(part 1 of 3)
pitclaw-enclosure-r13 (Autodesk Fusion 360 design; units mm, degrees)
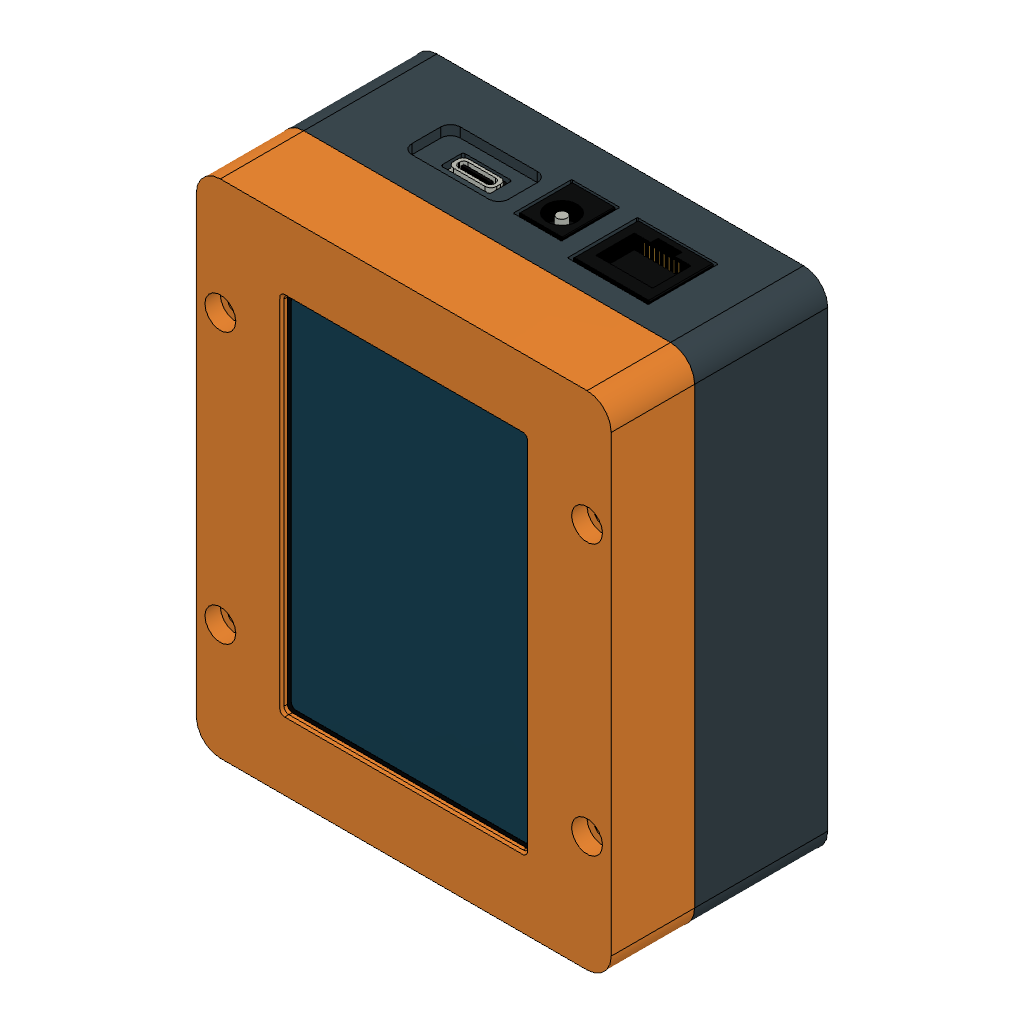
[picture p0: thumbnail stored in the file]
description: Part Number
part number: D_DO-41_SOD81_P10.16mm_Horizontal
part number: R_Axial_DIN0207_L6.3mm_D2.5mm_P7.62mm_Horizontal
part number: PinHeader_1x02_P2.54mm_Vertical
part number: TO-92_Inline_Wide
part number: JST_XH_B2B-XH-A_1x02_P2.50mm_Vertical
part number: JST_XH_B8B-XH-A_1x08_P2.50mm_Vertical
part number: pitclaw-carrier_pad
part number: pitclaw-carrier_silkscreen
part number: pitclaw-carrier_soldermask
parameter "floor_t" = 2.5 comment "PitClaw r8 nominal assembly datum; recheck fit after editing"
parameter "carrier_standoff" = 5 comment "PitClaw r8 nominal assembly datum; recheck fit after editing"
parameter "seam_z" = 27.6 comment "PitClaw r8 nominal assembly datum; recheck fit after editing"
parameter "case_h" = 44.9 comment "PitClaw r8 nominal assembly datum; recheck fit after editing"
parameter "retainer_t" = 2.5 comment "PitClaw r8 nominal assembly datum; recheck fit after editing"
parameter "retainer_top" = 32.6 comment "PitClaw r8 nominal assembly datum; recheck fit after editing"
parameter "retainer_bottom" = 30.1 (= "retainer_top - retainer_t") comment "PitClaw r8 nominal assembly datum; recheck fit after editing"
parameter "insert_pilot" = 4.2 comment "PitClaw r8 nominal assembly datum; recheck fit after editing"
parameter "insert_depth" = 5 comment "PitClaw r8 nominal assembly datum; recheck fit after editing"
parameter "lip_h" = 2 comment "PitClaw r8 nominal assembly datum; recheck fit after editing"
sketch "Outer shell profile" plane through (0, 0, 0) normal (0, 0, 1) x axis (1, 0, 0)
  line L1 (38, -52) -> (-38, -52)
  line L2 (43, 47) -> (43, -47)
  line L3 (-38, 52) -> (38, 52)
  line L4 (-43, -47) -> (-43, 47)
  arc A1 centre (38, -47) radius 5 clockwise from (43, -47) to (38, -52)
  arc A2 centre (38, 47) radius 5 clockwise from (38, 52) to (43, 47)
  arc A3 centre (-38, 47) radius 5 clockwise from (-43, 47) to (-38, 52)
  arc A4 centre (-38, -47) radius 5 clockwise from (-38, -52) to (-43, -47)
extrude "Extrude1" new body sketch "Outer shell profile" along normal blind 27.6 (= "seam_z") bodies "01 Bottom shell"
sketch "Open cavity profile" plane through (0, 0, 0) normal (0, 0, 1) x axis (1, 0, 0)
  line L1 (38, -49.5) -> (-38, -49.5)
  line L2 (40.5, 47) -> (40.5, -47)
  line L3 (-38, 49.5) -> (38, 49.5)
  line L4 (-40.5, -47) -> (-40.5, 47)
  arc A1 centre (38, -47) radius 2.5 clockwise from (40.5, -47) to (38, -49.5)
  arc A2 centre (38, 47) radius 2.5 clockwise from (38, 49.5) to (40.5, 47)
  arc A3 centre (-38, 47) radius 2.5 clockwise from (-40.5, 47) to (-38, 49.5)
  arc A4 centre (-38, -47) radius 2.5 clockwise from (-38, -49.5) to (-40.5, -47)
extrude "Extrude2" cut sketch "Open cavity profile" blind 27.6 (= "seam_z") from offset 2.5 (= "floor_t")
sketch "Four carrier insert bosses profile" plane through (0, 0, 0) normal (0, 0, 1) x axis (1, 0, 0)
  circle C1 centre (-25.5, -37) radius 4.5
  circle C2 centre (-25.5, 21) radius 4.5
  circle C3 centre (25.5, -37) radius 4.5
  circle C4 centre (25.5, 21) radius 4.5
extrude "Extrude3" add sketch "Four carrier insert bosses profile" blind 5 (= "carrier_standoff") from offset 2.5 (= "floor_t")
sketch "Four case closure columns profile" plane through (0, 0, 0) normal (0, 0, 1) x axis (1, 0, 0)
  circle C1 centre (-38, -28) radius 4.5
  circle C2 centre (-38, 28) radius 4.5
  circle C3 centre (38, -28) radius 4.5
  circle C4 centre (38, 28) radius 4.5
extrude "Extrude4" add sketch "Four case closure columns profile" blind 25.1 (= "seam_z - floor_t") from offset 2.5 (= "floor_t")
sketch "USB recess internal backing profile" plane through (0, 0, 0) normal (0, 1, 0) x axis (1, 0, 0)
  line L1 (22.5, -10.7) -> (6.5, -10.7)
  line L2 (24.5, -18.7) -> (24.5, -12.7)
  line L3 (6.5, -20.7) -> (22.5, -20.7)
  line L4 (4.5, -12.7) -> (4.5, -18.7)
  arc A1 centre (22.5, -12.7) radius 2 clockwise from (22.5, -10.7) to (24.5, -12.7)
  arc A2 centre (22.5, -18.7) radius 2 clockwise from (24.5, -18.7) to (22.5, -20.7)
  arc A3 centre (6.5, -18.7) radius 2 clockwise from (6.5, -20.7) to (4.5, -18.7)
  arc A4 centre (6.5, -12.7) radius 2 clockwise from (4.5, -12.7) to (6.5, -10.7)
extrude "Extrude5" add sketch "USB recess internal backing profile" blind 1.02 from offset 48.5
sketch "Carrier insert pilots profile" plane through (0, 0, 0) normal (0, 0, 1) x axis (1, 0, 0)
  circle C1 centre (-25.5, -37) radius 2.1
  circle C2 centre (-25.5, 21) radius 2.1
  circle C3 centre (25.5, -37) radius 2.1
  circle C4 centre (25.5, 21) radius 2.1
  dimension "d127" diameter C1 = 4.2 (= "insert_pilot")
  dimension "d128" diameter C2 = 4.2 (= "insert_pilot")
  dimension "d129" diameter C3 = 4.2 (= "insert_pilot")
  dimension "d130" diameter C4 = 4.2 (= "insert_pilot")
extrude "Extrude6" cut sketch "Carrier insert pilots profile" blind 5.02 from offset 2.5 (= "floor_t")
sketch "Closure insert pilots profile" plane through (0, 0, 0) normal (0, 0, 1) x axis (1, 0, 0)
  circle C1 centre (-38, -28) radius 2.1
  circle C2 centre (-38, 28) radius 2.1
  circle C3 centre (38, -28) radius 2.1
  circle C4 centre (38, 28) radius 2.1
  dimension "d131" diameter C1 = 4.2 (= "insert_pilot")
  dimension "d132" diameter C2 = 4.2 (= "insert_pilot")
  dimension "d133" diameter C3 = 4.2 (= "insert_pilot")
  dimension "d134" diameter C4 = 4.2 (= "insert_pilot")
extrude "Extrude7" cut sketch "Closure insert pilots profile" blind 5.02 from offset 22.6 (= "seam_z - insert_depth")
sketch "Three probe access holes profile" plane through (0, 0, 0) normal (0, 1, 0) x axis (1, 0, 0)
  circle C1 centre (-17, -11.65) radius 5.25
  circle C2 centre (0, -11.65) radius 5.25
  circle C3 centre (17, -11.65) radius 5.25
extrude "Extrude8" cut sketch "Three probe access holes profile" blind 10 from offset -57
sketch "RJ45 fitted opening profile" plane through (0, 0, 0) normal (0, 1, 0) x axis (1, 0, 0)
  line L1 (-12.325, -8.6) -> (-28.675, -8.6)
  line L2 (-12.125, -22.91) -> (-12.125, -8.8)
  line L3 (-28.675, -23.11) -> (-12.325, -23.11)
  line L4 (-28.875, -8.8) -> (-28.875, -22.91)
  arc A1 centre (-12.325, -8.8) radius 0.2 clockwise from (-12.325, -8.6) to (-12.125, -8.8)
  arc A2 centre (-12.325, -22.91) radius 0.2 clockwise from (-12.125, -22.91) to (-12.325, -23.11)
  arc A3 centre (-28.675, -22.91) radius 0.2 clockwise from (-28.675, -23.11) to (-28.875, -22.91)
  arc A4 centre (-28.675, -8.8) radius 0.2 clockwise from (-28.875, -8.8) to (-28.675, -8.6)
extrude "Extrude9" cut sketch "RJ45 fitted opening profile" blind 10 from offset 47
sketch "Barrel fitted opening profile" plane through (0, 0, 0) normal (0, 1, 0) x axis (1, 0, 0)
  line L1 (1.3, -8.6) -> (-8.3, -8.6)
  line L2 (1.5, -20.5) -> (1.5, -8.8)
  line L3 (-8.3, -20.7) -> (1.3, -20.7)
  line L4 (-8.5, -8.8) -> (-8.5, -20.5)
  arc A1 centre (1.3, -8.8) radius 0.2 clockwise from (1.3, -8.6) to (1.5, -8.8)
  arc A2 centre (1.3, -20.5) radius 0.2 clockwise from (1.5, -20.5) to (1.3, -20.7)
  arc A3 centre (-8.3, -20.5) radius 0.2 clockwise from (-8.3, -20.7) to (-8.5, -20.5)
  arc A4 centre (-8.3, -8.8) radius 0.2 clockwise from (-8.5, -8.8) to (-8.3, -8.6)
extrude "Extrude10" cut sketch "Barrel fitted opening profile" blind 10 from offset 47
sketch "USB fitted shell aperture profile" plane through (0, 0, 0) normal (0, 1, 0) x axis (1, 0, 0)
  line L1 (19.17, -13) -> (9.83, -13)
  line L2 (19.57, -17.3) -> (19.57, -13.4)
  line L3 (9.83, -17.7) -> (19.17, -17.7)
  line L4 (9.43, -13.4) -> (9.43, -17.3)
  arc A1 centre (19.17, -13.4) radius 0.4 clockwise from (19.17, -13) to (19.57, -13.4)
  arc A2 centre (19.17, -17.3) radius 0.4 clockwise from (19.57, -17.3) to (19.17, -17.7)
  arc A3 centre (9.83, -17.3) radius 0.4 clockwise from (9.83, -17.7) to (9.43, -17.3)
  arc A4 centre (9.83, -13.4) radius 0.4 clockwise from (9.43, -13.4) to (9.83, -13)
extrude "Extrude11" cut sketch "USB fitted shell aperture profile" blind 10 from offset 47
sketch "USB shallow external recess profile" plane through (0, 0, 0) normal (0, 1, 0) x axis (1, 0, 0)
  line L1 (22.5, -10.7) -> (6.5, -10.7)
  line L2 (24.5, -18.7) -> (24.5, -12.7)
  line L3 (6.5, -20.7) -> (22.5, -20.7)
  line L4 (4.5, -12.7) -> (4.5, -18.7)
  arc A1 centre (22.5, -12.7) radius 2 clockwise from (22.5, -10.7) to (24.5, -12.7)
  arc A2 centre (22.5, -18.7) radius 2 clockwise from (24.5, -18.7) to (22.5, -20.7)
  arc A3 centre (6.5, -18.7) radius 2 clockwise from (6.5, -20.7) to (4.5, -18.7)
  arc A4 centre (6.5, -12.7) radius 2 clockwise from (4.5, -12.7) to (6.5, -10.7)
extrude "Extrude12" cut sketch "USB shallow external recess profile" blind 2.02 from offset 50
sketch "Hidden carrier edge channel profile" plane through (0, 0, 0) normal (0, 0, 1) x axis (1, 0, 0)
  line L1 (30.5, 49.48) -> (-30.5, 49.48)
  line L2 (30.5, 51) -> (30.5, 49.48)
  line L3 (-30.5, 51) -> (30.5, 51)
  line L4 (-30.5, 49.48) -> (-30.5, 51)
extrude "Extrude13" cut sketch "Hidden carrier edge channel profile" blind 2.9 from offset 7
sketch "Hidden USB PCB edge clearance profile" plane through (0, 0, 0) normal (0, 0, 1) x axis (1, 0, 0)
  line L1 (24.86, 48.48) -> (4.14, 48.48)
  line L2 (24.86, 49.057) -> (24.86, 48.48)
  line L3 (4.14, 49.057) -> (24.86, 49.057)
  line L4 (4.14, 48.48) -> (4.14, 49.057)
extrude "Extrude14" cut sketch "Hidden USB PCB edge clearance profile" blind 3.5 from offset 11.3
sketch "Hidden USB spacer and head clearances profile" plane through (0, 0, 0) normal (0, 0, 1) x axis (1, 0, 0)
  circle C1 centre (6.753, 46.317) radius 2.7
  circle C2 centre (21.993, 46.317) radius 2.7
extrude "Extrude15" cut sketch "Hidden USB spacer and head clearances profile" blind 8.5 from offset 8.3
sketch "Power edge support -28 profile" plane through (0, 0, 0) normal (0, 0, 1) x axis (1, 0, 0)
  line L1 (-25, 49.2) -> (-28, 49.2)
  line L2 (-25, 50.5) -> (-25, 49.2)
  line L3 (-28, 50.5) -> (-25, 50.5)
  line L4 (-28, 49.2) -> (-28, 50.5)
extrude "Extrude16" add sketch "Power edge support -28 profile" blind 5 (= "carrier_standoff") from offset 2.5 (= "floor_t")
sketch "Power edge support 26 profile" plane through (0, 0, 0) normal (0, 0, 1) x axis (1, 0, 0)
  line L1 (29, 49.2) -> (26, 49.2)
  line L2 (29, 50.5) -> (29, 49.2)
  line L3 (26, 50.5) -> (29, 50.5)
  line L4 (26, 49.2) -> (26, 50.5)
extrude "Extrude17" add sketch "Power edge support 26 profile" blind 5 (= "carrier_standoff") from offset 2.5 (= "floor_t")
sketch "Top outer cup profile" plane through (0, 0, 0) normal (0, 0, 1) x axis (1, 0, 0)
  line L1 (38, -52) -> (-38, -52)
  line L2 (43, 47) -> (43, -47)
  line L3 (-38, 52) -> (38, 52)
  line L4 (-43, -47) -> (-43, 47)
  arc A1 centre (38, -47) radius 5 clockwise from (43, -47) to (38, -52)
  arc A2 centre (38, 47) radius 5 clockwise from (38, 52) to (43, 47)
  arc A3 centre (-38, 47) radius 5 clockwise from (-43, 47) to (-38, 52)
  arc A4 centre (-38, -47) radius 5 clockwise from (-38, -52) to (-43, -47)
extrude "Extrude1" new body sketch "Top outer cup profile" blind 17.3 (= "case_h - seam_z") from offset 27.6 (= "seam_z") bodies "02 Top bezel - fitted lip and 4.2mm pilots"
sketch "Top inner cavity profile" plane through (0, 0, 0) normal (0, 0, 1) x axis (1, 0, 0)
  line L1 (38, -49.5) -> (-38, -49.5)
  line L2 (40.5, 47) -> (40.5, -47)
  line L3 (-38, 49.5) -> (38, 49.5)
  line L4 (-40.5, -47) -> (-40.5, 47)
  arc A1 centre (38, -47) radius 2.5 clockwise from (40.5, -47) to (38, -49.5)
  arc A2 centre (38, 47) radius 2.5 clockwise from (38, 49.5) to (40.5, 47)
  arc A3 centre (-38, 47) radius 2.5 clockwise from (-40.5, 47) to (-38, 49.5)
  arc A4 centre (-38, -47) radius 2.5 clockwise from (-38, -49.5) to (-40.5, -47)
extrude "Extrude2" cut sketch "Top inner cavity profile" blind 14.32 (= "case_h - 3 mm - seam_z + 0.02 mm") from offset 27.58 (= "seam_z - 0.02 mm")
sketch "Locating lip connecting shoulder profile" plane through (0, 0, 0) normal (0, 0, 1) x axis (1, 0, 0)
  line L1 (38, -52) -> (-38, -52)
  line L2 (43, 47) -> (43, -47)
  line L3 (-38, 52) -> (38, 52)
  line L4 (-43, -47) -> (-43, 47)
  line L5 (35, -48) -> (-35, -48)
  line L6 (39, 44) -> (39, -44)
  line L7 (-35, 48) -> (35, 48)
  line L8 (-39, -44) -> (-39, 44)
  arc A1 centre (38, -47) radius 5 clockwise from (43, -47) to (38, -52)
  arc A2 centre (38, 47) radius 5 clockwise from (38, 52) to (43, 47)
  arc A3 centre (-38, 47) radius 5 clockwise from (-43, 47) to (-38, 52)
  arc A4 centre (-38, -47) radius 5 clockwise from (-38, -52) to (-43, -47)
  arc A5 centre (35, -44) radius 4 clockwise from (39, -44) to (35, -48)
  arc A6 centre (35, 44) radius 4 clockwise from (35, 48) to (39, 44)
  arc A7 centre (-35, 44) radius 4 clockwise from (-39, 44) to (-35, 48)
  arc A8 centre (-35, -44) radius 4 clockwise from (-35, -48) to (-39, -44)
extrude "Extrude3" add sketch "Locating lip connecting shoulder profile" blind 1 from offset 27.6 (= "seam_z")
sketch "Locating lip profile" plane through (0, 0, 0) normal (0, 0, 1) x axis (1, 0, 0)
  line L1 (38.2, -49.2) -> (-38.2, -49.2)
  line L2 (40.2, 47.2) -> (40.2, -47.2)
  line L3 (-38.2, 49.2) -> (38.2, 49.2)
  line L4 (-40.2, -47.2) -> (-40.2, 47.2)
  line L5 (38, -48) -> (-38, -48)
  line L6 (39, 47) -> (39, -47)
  line L7 (-38, 48) -> (38, 48)
  line L8 (-39, -47) -> (-39, 47)
  arc A1 centre (38.2, -47.2) radius 2 clockwise from (40.2, -47.2) to (38.2, -49.2)
  arc A2 centre (38.2, 47.2) radius 2 clockwise from (38.2, 49.2) to (40.2, 47.2)
  arc A3 centre (-38.2, 47.2) radius 2 clockwise from (-40.2, 47.2) to (-38.2, 49.2)
  arc A4 centre (-38.2, -47.2) radius 2 clockwise from (-38.2, -49.2) to (-40.2, -47.2)
  arc A5 centre (38, -47) radius 1 clockwise from (39, -47) to (38, -48)
  arc A6 centre (38, 47) radius 1 clockwise from (38, 48) to (39, 47)
  arc A7 centre (-38, 47) radius 1 clockwise from (-39, 47) to (-38, 48)
  arc A8 centre (-38, -47) radius 1 clockwise from (-38, -48) to (-39, -47)
extrude "Extrude4" add sketch "Locating lip profile" blind 2.02 (= "lip_h + 0.02 mm") from offset 25.6 (= "seam_z - lip_h")
sketch "Lip relief around closure columns profile" plane through (0, 0, 0) normal (0, 0, 1) x axis (1, 0, 0)
  circle C1 centre (-38, -28) radius 5
  circle C2 centre (-38, 28) radius 5
  circle C3 centre (38, -28) radius 5
  circle C4 centre (38, 28) radius 5
extrude "Extrude5" cut sketch "Lip relief around closure columns profile" blind 2.02 (= "lip_h + 0.02 mm") from offset 25.58 (= "seam_z - lip_h - 0.02 mm")
sketch "Four independent closure columns profile" plane through (0, 0, 0) normal (0, 0, 1) x axis (1, 0, 0)
  circle C1 centre (-38, -28) radius 4.5
  circle C2 centre (-38, 28) radius 4.5
  circle C3 centre (38, -28) radius 4.5
  circle C4 centre (38, 28) radius 4.5
extrude "Extrude6" add sketch "Four independent closure columns profile" blind 17.3 (= "case_h - seam_z") from offset 27.6 (= "seam_z")
sketch "Four display retainer hard stops profile" plane through (0, 0, 0) normal (0, 0, 1) x axis (1, 0, 0)
  circle C1 centre (-35.5, -40) radius 4.5
  circle C2 centre (-35.5, 40) radius 4.5
  circle C3 centre (35.5, -40) radius 4.5
  circle C4 centre (35.5, 40) radius 4.5
extrude "Extrude7" add sketch "Four display retainer hard stops profile" blind 12.3 (= "case_h - retainer_top") from offset 32.6 (= "retainer_top")
sketch "Display body and glass pocket profile" plane through (0, 0, 0) normal (0, 0, 1) x axis (1, 0, 0)
  line L1 (29.1, -46.6) -> (-29.1, -46.6)
  line L2 (30.6, 45.1) -> (30.6, -45.1)
  line L3 (-29.1, 46.6) -> (29.1, 46.6)
  line L4 (-30.6, -45.1) -> (-30.6, 45.1)
  arc A1 centre (29.1, -45.1) radius 1.5 clockwise from (30.6, -45.1) to (29.1, -46.6)
  arc A2 centre (29.1, 45.1) radius 1.5 clockwise from (29.1, 46.6) to (30.6, 45.1)
  arc A3 centre (-29.1, 45.1) radius 1.5 clockwise from (-30.6, 45.1) to (-29.1, 46.6)
  arc A4 centre (-29.1, -45.1) radius 1.5 clockwise from (-29.1, -46.6) to (-30.6, -45.1)
extrude "Extrude8" cut sketch "Display body and glass pocket profile" blind 16.12 from offset 27.58 (= "seam_z - 0.02 mm")
sketch "Active display window profile" plane through (0, 0, 0) normal (0, 0, 1) x axis (1, 0, 0)
  line L1 (24.3, -37.55) -> (-24.3, -37.55)
  line L2 (25.3, 36.55) -> (25.3, -36.55)
  line L3 (-24.3, 37.55) -> (24.3, 37.55)
  line L4 (-25.3, -36.55) -> (-25.3, 36.55)
  arc A1 centre (24.3, -36.55) radius 1 clockwise from (25.3, -36.55) to (24.3, -37.55)
  arc A2 centre (24.3, 36.55) radius 1 clockwise from (24.3, 37.55) to (25.3, 36.55)
  arc A3 centre (-24.3, 36.55) radius 1 clockwise from (-25.3, 36.55) to (-24.3, 37.55)
  arc A4 centre (-24.3, -36.55) radius 1 clockwise from (-24.3, -37.55) to (-25.3, -36.55)
extrude "Extrude9" cut sketch "Active display window profile" blind 1.24 from offset 43.68
work_plane "WorkPlane1" AlongDistance 44.4 ExtraOffset 0
sketch "Front window bevel start profile" plane through (0, 0, 44.4) normal (0, 0, 1) x axis (1, 0, 0)
  line L1 (24.3, -37.55) -> (-24.3, -37.55)
  line L2 (25.3, 36.55) -> (25.3, -36.55)
  line L3 (-24.3, 37.55) -> (24.3, 37.55)
  line L4 (-25.3, -36.55) -> (-25.3, 36.55)
  arc A1 centre (24.3, -36.55) radius 1 clockwise from (25.3, -36.55) to (24.3, -37.55)
  arc A2 centre (24.3, 36.55) radius 1 clockwise from (24.3, 37.55) to (25.3, 36.55)
  arc A3 centre (-24.3, 36.55) radius 1 clockwise from (-25.3, 36.55) to (-24.3, 37.55)
  arc A4 centre (-24.3, -36.55) radius 1 clockwise from (-24.3, -37.55) to (-25.3, -36.55)
work_plane "WorkPlane2" AlongDistance 44.92 ExtraOffset 0
sketch "Front window bevel end profile" plane through (0, 0, 44.92) normal (0, 0, 1) x axis (1, 0, 0)
  line L1 (24.6695, -37.9255) -> (-24.6695, -37.9255)
  line L2 (25.6795, 36.9155) -> (25.6795, -36.9155)
  line L3 (-24.6695, 37.9255) -> (24.6695, 37.9255)
  line L4 (-25.6795, -36.9155) -> (-25.6795, 36.9155)
  arc A1 centre (24.6695, -36.9155) radius 1.01 clockwise from (25.6795, -36.9155) to (24.6695, -37.9255)
  arc A2 centre (24.6695, 36.9155) radius 1.01 clockwise from (24.6695, 37.9255) to (25.6795, 36.9155)
  arc A3 centre (-24.6695, 36.9155) radius 1.01 clockwise from (-25.6795, 36.9155) to (-24.6695, 37.9255)
  arc A4 centre (-24.6695, -36.9155) radius 1.01 clockwise from (-24.6695, -37.9255) to (-25.6795, -36.9155)
loft "Loft1" sketch "Front window bevel start profile" + "Front window bevel end profile"
sketch "Case screw clearance holes profile" plane through (0, 0, 0) normal (0, 0, 1) x axis (1, 0, 0)
  circle C1 centre (-38, -28) radius 1.7
  circle C2 centre (-38, 28) radius 1.7
  circle C3 centre (38, -28) radius 1.7
  circle C4 centre (38, 28) radius 1.7
extrude "Extrude10" cut sketch "Case screw clearance holes profile" blind 17.34 (= "case_h - seam_z + 0.04 mm") from offset 27.58 (= "seam_z - 0.02 mm")
sketch "Case screw head recesses profile" plane through (0, 0, 0) normal (0, 0, 1) x axis (1, 0, 0)
  circle C1 centre (-38, -28) radius 3.2
  circle C2 centre (-38, 28) radius 3.2
  circle C3 centre (38, -28) radius 3.2
  circle C4 centre (38, 28) radius 3.2
extrude "Extrude11" cut sketch "Case screw head recesses profile" blind 3.22 from offset 41.7 (= "case_h - 3.2 mm")
sketch "Four retainer insert pilots profile" plane through (0, 0, 0) normal (0, 0, 1) x axis (1, 0, 0)
  circle C1 centre (-35.5, -40) radius 2.1
  circle C2 centre (-35.5, 40) radius 2.1
  circle C3 centre (35.5, -40) radius 2.1
  circle C4 centre (35.5, 40) radius 2.1
  dimension "d135" diameter C1 = 4.2 (= "insert_pilot")
  dimension "d136" diameter C2 = 4.2 (= "insert_pilot")
  dimension "d137" diameter C3 = 4.2 (= "insert_pilot")
  dimension "d138" diameter C4 = 4.2 (= "insert_pilot")
extrude "Extrude12" cut sketch "Four retainer insert pilots profile" blind 5.02 (= "insert_depth + 0.02 mm") from offset 32.58 (= "retainer_top - 0.02 mm")
sketch "Retainer insertion relief profile" plane through (0, 0, 0) normal (0, 0, 1) x axis (1, 0, 0)
  line L1 (34.4, -48.5) -> (-34.4, -48.5)
  line L2 (35.4, 47.5) -> (35.4, -47.5)
  line L3 (-34.4, 48.5) -> (34.4, 48.5)
  line L4 (-35.4, -47.5) -> (-35.4, 47.5)
  arc A1 centre (34.4, -47.5) radius 1 clockwise from (35.4, -47.5) to (34.4, -48.5)
  arc A2 centre (34.4, 47.5) radius 1 clockwise from (34.4, 48.5) to (35.4, 47.5)
  arc A3 centre (-34.4, 47.5) radius 1 clockwise from (-35.4, 47.5) to (-34.4, 48.5)
  arc A4 centre (-34.4, -47.5) radius 1 clockwise from (-34.4, -48.5) to (-35.4, -47.5)
extrude "Extrude13" cut sketch "Retainer insertion relief profile" blind 3.04 (= "lip_h + 1.04 mm") from offset 25.58 (= "seam_z - lip_h - 0.02 mm")
sketch "Four anchor pad insertion reliefs profile" plane through (0, 0, 0) normal (0, 0, 1) x axis (1, 0, 0)
  circle C1 centre (-35.5, -40) radius 5
  circle C2 centre (-35.5, 40) radius 5
  circle C3 centre (35.5, -40) radius 5
  circle C4 centre (35.5, 40) radius 5
extrude "Extrude14" cut sketch "Four anchor pad insertion reliefs profile" blind 3.04 (= "lip_h + 1.04 mm") from offset 25.58 (= "seam_z - lip_h - 0.02 mm")
sketch "Thin perimeter frame profile" plane through (0, 0, 0) normal (0, 0, 1) x axis (1, 0, 0)
  line L1 (34, -48) -> (-34, -48)
  line L2 (35, 47) -> (35, -47)
  line L3 (-34, 48) -> (34, 48)
  line L4 (-35, -47) -> (-35, 47)
  line L5 (30, -46.4) -> (-30, -46.4)
  line L6 (30.4, 46) -> (30.4, -46)
  line L7 (-30, 46.4) -> (30, 46.4)
  line L8 (-30.4, -46) -> (-30.4, 46)
  arc A1 centre (34, -47) radius 1 clockwise from (35, -47) to (34, -48)
  arc A2 centre (34, 47) radius 1 clockwise from (34, 48) to (35, 47)
  arc A3 centre (-34, 47) radius 1 clockwise from (-35, 47) to (-34, 48)
  arc A4 centre (-34, -47) radius 1 clockwise from (-34, -48) to (-35, -47)
  arc A5 centre (30, -46) radius 0.4 clockwise from (30.4, -46) to (30, -46.4)
  arc A6 centre (30, 46) radius 0.4 clockwise from (30, 46.4) to (30.4, 46)
  arc A7 centre (-30, 46) radius 0.4 clockwise from (-30.4, 46) to (-30, 46.4)
  arc A8 centre (-30, -46) radius 0.4 clockwise from (-30, -46.4) to (-30.4, -46)
extrude "Extrude1" new body sketch "Thin perimeter frame profile" blind 2.5 (= "retainer_t") from offset 30.1 (= "retainer_bottom") bodies "03 WT32 retainer - four anchors"
sketch "Four OEM mounting pads and rail ties profile" plane through (0, 0, 0) normal (0, 0, 1) x axis (1, 0, 0)
  line L1 (-26.9131, -36.5209) -> (-32.3045, -38.7402)
  line L2 (-32.3045, -40.2198) -> (-26.9131, -42.4391)
  line L3 (-26.9131, 38.6191) -> (-32.3045, 36.3998)
  line L4 (-32.3045, 34.9202) -> (-26.9131, 32.7009)
  line L5 (32.3045, -38.7402) -> (26.9131, -36.5209)
  line L6 (26.9131, -42.4391) -> (32.3045, -40.2198)
  line L7 (32.3045, 36.3998) -> (26.9131, 38.6191)
  line L8 (26.9131, 32.7009) -> (32.3045, 34.9202)
  arc A1 centre (-25.695, -39.48) radius 3.2 clockwise from (-26.9131, -36.5209) to (-26.9131, -42.4391)
  arc A2 centre (-32, -39.48) radius 0.8 clockwise from (-32.3045, -40.2198) to (-32.3045, -38.7402)
  arc A3 centre (-25.695, 35.66) radius 3.2 clockwise from (-26.9131, 38.6191) to (-26.9131, 32.7009)
  arc A4 centre (-32, 35.66) radius 0.8 clockwise from (-32.3045, 34.9202) to (-32.3045, 36.3998)
  arc A5 centre (32, -39.48) radius 0.8 clockwise from (32.3045, -38.7402) to (32.3045, -40.2198)
  arc A6 centre (25.695, -39.48) radius 3.2 clockwise from (26.9131, -42.4391) to (26.9131, -36.5209)
  arc A7 centre (32, 35.66) radius 0.8 clockwise from (32.3045, 36.3998) to (32.3045, 34.9202)
  arc A8 centre (25.695, 35.66) radius 3.2 clockwise from (26.9131, 32.7009) to (26.9131, 38.6191)
extrude "Extrude2" add sketch "Four OEM mounting pads and rail ties profile" blind 2.5 (= "retainer_t") from offset 30.1 (= "retainer_bottom")
sketch "Four case anchor pads profile" plane through (0, 0, 0) normal (0, 0, 1) x axis (1, 0, 0)
  circle C1 centre (-35.5, -40) radius 4.5
  circle C2 centre (-35.5, 40) radius 4.5
  circle C3 centre (35.5, -40) radius 4.5
  circle C4 centre (35.5, 40) radius 4.5
extrude "Extrude3" add sketch "Four case anchor pads profile" blind 2.5 (= "retainer_t") from offset 30.1 (= "retainer_bottom")
sketch "Closure column scallops profile" plane through (0, 0, 0) normal (0, 0, 1) x axis (1, 0, 0)
  circle C1 centre (-38, -28) radius 5
  circle C2 centre (-38, 28) radius 5
  circle C3 centre (38, -28) radius 5
  circle C4 centre (38, 28) radius 5
extrude "Extrude4" cut sketch "Closure column scallops profile" blind 2.54 (= "retainer_t + 0.04 mm") from offset 30.08 (= "retainer_bottom - 0.02 mm")
sketch "WT32 rear blind boss screw clearances profile" plane through (0, 0, 0) normal (0, 0, 1) x axis (1, 0, 0)
  circle C1 centre (-25.695, -39.48) radius 1.4
  circle C2 centre (-25.695, 35.66) radius 1.4
  circle C3 centre (25.695, -39.48) radius 1.4
  circle C4 centre (25.695, 35.66) radius 1.4
extrude "Extrude5" cut sketch "WT32 rear blind boss screw clearances profile" blind 2.54 (= "retainer_t + 0.04 mm") from offset 30.08 (= "retainer_bottom - 0.02 mm")
sketch "Four M3 anchor screw clearances profile" plane through (0, 0, 0) normal (0, 0, 1) x axis (1, 0, 0)
  circle C1 centre (-35.5, -40) radius 1.7
  circle C2 centre (-35.5, 40) radius 1.7
  circle C3 centre (35.5, -40) radius 1.7
  circle C4 centre (35.5, 40) radius 1.7
extrude "Extrude6" cut sketch "Four M3 anchor screw clearances profile" blind 2.54 (= "retainer_t + 0.04 mm") from offset 30.08 (= "retainer_bottom - 0.02 mm")
sketch "Nominal carrier outline profile" plane through (0, 0, 0) normal (0, 0, 1) x axis (1, 0, 0)
  line L1 (30, -41.5) -> (-30, -41.5)
  line L2 (30, 50.5) -> (30, -41.5)
  line L3 (-30, 50.5) -> (30, 50.5)
  line L4 (-30, -41.5) -> (-30, 50.5)
extrude "Extrude1" new body sketch "Nominal carrier outline profile" blind 1.6 from offset 7.5 bodies "Carrier PCB - placed components omitted"
sketch "Carrier mounting holes profile" plane through (0, 0, 0) normal (0, 0, 1) x axis (1, 0, 0)
  circle C1 centre (-25.5, -37) radius 1.6
  circle C2 centre (-25.5, 21) radius 1.6
  circle C3 centre (25.5, -37) radius 1.6
  circle C4 centre (25.5, 21) radius 1.6
extrude "Extrude2" cut sketch "Carrier mounting holes profile" blind 1.64 from offset 7.48
sketch "Display glass outline profile" plane through (0, 0, 0) normal (0, 0, 1) x axis (1, 0, 0)
  line L1 (28.5, -46) -> (-28.5, -46)
  line L2 (30, 44.5) -> (30, -44.5)
  line L3 (-28.5, 46) -> (28.5, 46)
  line L4 (-30, -44.5) -> (-30, 44.5)
  arc A1 centre (28.5, -44.5) radius 1.5 clockwise from (30, -44.5) to (28.5, -46)
  arc A2 centre (28.5, 44.5) radius 1.5 clockwise from (28.5, 46) to (30, 44.5)
  arc A3 centre (-28.5, 44.5) radius 1.5 clockwise from (-30, 44.5) to (-28.5, 46)
  arc A4 centre (-28.5, -44.5) radius 1.5 clockwise from (-28.5, -46) to (-30, -44.5)
extrude "Extrude1" new body sketch "Display glass outline profile" blind 1.45 from offset 41.95 bodies "WT32 nominal envelope - sample verification required"
sketch "Active display area profile" plane through (0, 0, 0) normal (0, 0, 1) x axis (1, 0, 0)
  line L1 (23.78, -37.02) -> (-23.78, -37.02)
  line L2 (24.78, 36.02) -> (24.78, -36.02)
  line L3 (-23.78, 37.02) -> (23.78, 37.02)
  line L4 (-24.78, -36.02) -> (-24.78, 36.02)
  arc A1 centre (23.78, -36.02) radius 1 clockwise from (24.78, -36.02) to (23.78, -37.02)
  arc A2 centre (23.78, 36.02) radius 1 clockwise from (23.78, 37.02) to (24.78, 36.02)
  arc A3 centre (-23.78, 36.02) radius 1 clockwise from (-24.78, 36.02) to (-23.78, 37.02)
  arc A4 centre (-23.78, -36.02) radius 1 clockwise from (-23.78, -37.02) to (-24.78, -36.02)
extrude "Extrude2" new body sketch "Active display area profile" blind 0.03 from offset 43.4
sketch "Display frame envelope profile" plane through (0, 0, 0) normal (0, 0, 1) x axis (1, 0, 0)
  line L1 (28.5, -46) -> (-28.5, -46)
  line L2 (30, 44.5) -> (30, -44.5)
  line L3 (-28.5, 46) -> (28.5, 46)
  line L4 (-30, -44.5) -> (-30, 44.5)
  line L5 (26, -41) -> (-26, -41)
  line L6 (26.5, 40.5) -> (26.5, -40.5)
  line L7 (-26, 41) -> (26, 41)
  line L8 (-26.5, -40.5) -> (-26.5, 40.5)
  arc A1 centre (28.5, -44.5) radius 1.5 clockwise from (30, -44.5) to (28.5, -46)
  arc A2 centre (28.5, 44.5) radius 1.5 clockwise from (28.5, 46) to (30, 44.5)
  arc A3 centre (-28.5, 44.5) radius 1.5 clockwise from (-30, 44.5) to (-28.5, 46)
  arc A4 centre (-28.5, -44.5) radius 1.5 clockwise from (-28.5, -46) to (-30, -44.5)
  arc A5 centre (26, -40.5) radius 0.5 clockwise from (26.5, -40.5) to (26, -41)
  arc A6 centre (26, 40.5) radius 0.5 clockwise from (26, 41) to (26.5, 40.5)
  arc A7 centre (-26, 40.5) radius 0.5 clockwise from (-26.5, 40.5) to (-26, 41)
  arc A8 centre (-26, -40.5) radius 0.5 clockwise from (-26, -41) to (-26.5, -40.5)
extrude "Extrude3" new body sketch "Display frame envelope profile" blind 3.35 from offset 38.6
sketch "Display rear PCB envelope profile" plane through (0, 0, 0) normal (0, 0, 1) x axis (1, 0, 0)
  line L1 (24, -35) -> (-24, -35)
  line L2 (24, 35) -> (24, -35)
  line L3 (-24, 35) -> (24, 35)
  line L4 (-24, -35) -> (-24, 35)
extrude "Extrude4" new body sketch "Display rear PCB envelope profile" blind 1.6 from offset 32.6
sketch "Four rear mounting boss envelopes profile" plane through (0, 0, 0) normal (0, 0, 1) x axis (1, 0, 0)
  circle C1 centre (-25.695, -39.48) radius 2.9
  circle C2 centre (-25.695, 35.66) radius 2.9
  circle C3 centre (25.695, -39.48) radius 2.9
  circle C4 centre (25.695, 35.66) radius 2.9
extrude "Extrude5" new body sketch "Four rear mounting boss envelopes profile" blind 6 from offset 32.6
combine "Combine1"
base_feature "Base Feature1"
base_feature "Base Feature1"
base_feature "Base Feature1"
base_feature "Base Feature1"
base_feature "Base Feature1"
base_feature "Base Feature1"
base_feature "Base Feature1"
base_feature "Base Feature1"
base_feature "Base Feature1"
base_feature "Base Feature1"
base_feature "Base Feature1"
base_feature "Base Feature1"
base_feature "Base Feature1"
mirror "Mirror1" mirrorStitchTolerance 0.01 bodies "01 Bottom shell - fitted guides and 4.2mm pilots"
remove_body "RemoveBody1"
sketch "C1 electrolytic sleeve profile" plane through (0, 0, 0) normal (0, 0, 1) x axis (1, 0, 0)
  circle C1 centre (-15.5, 17.5) radius 5
extrude "Extrude1" new body sketch "C1 electrolytic sleeve profile" blind 12.5 from offset 9.4 bodies "C1 electrolytic sleeve"
sketch "C1 aluminum top profile" plane through (0, 0, 0) normal (0, 0, 1) x axis (1, 0, 0)
  circle C1 centre (-15.5, 17.5) radius 4.8
extrude "Extrude2" new body sketch "C1 aluminum top profile" blind 0.16 from offset 21.75 bodies "C1 aluminum top"
sketch "C1 leads profile" plane through (0, 0, 0) normal (0, 0, 1) x axis (1, 0, 0)
  circle C1 centre (-13, 17.5) radius 0.3
  circle C2 centre (-18, 17.5) radius 0.3
extrude "Extrude3" new body sketch "C1 leads profile" blind 3.5 from offset 6.5 bodies "C1 leads", "C1 leads (1)"
sketch "C3 electrolytic sleeve profile" plane through (0, 0, 0) normal (0, 0, 1) x axis (1, 0, 0)
  circle C1 centre (-25, -27) radius 4
extrude "Extrude1" new body sketch "C3 electrolytic sleeve profile" blind 11.5 from offset 9.4 bodies "C3 electrolytic sleeve"
sketch "C3 aluminum top profile" plane through (0, 0, 0) normal (0, 0, 1) x axis (1, 0, 0)
  circle C1 centre (-25, -27) radius 3.8
extrude "Extrude2" new body sketch "C3 aluminum top profile" blind 0.16 from offset 20.75 bodies "C3 aluminum top"
sketch "C3 leads profile" plane through (0, 0, 0) normal (0, 0, 1) x axis (1, 0, 0)
  circle C1 centre (-23.25, -27) radius 0.3
  circle C2 centre (-26.75, -27) radius 0.3
extrude "Extrude3" new body sketch "C3 leads profile" blind 3.5 from offset 6.5 bodies "C3 leads", "C3 leads (1)"
sketch "C2 ceramic body profile" plane through (0, 0, 0) normal (0, 0, 1) x axis (1, 0, 0)
  line L1 (14.15, 22.25) -> (10.85, 22.25)
  line L2 (14.5, 24.4) -> (14.5, 22.6)
  line L3 (10.85, 24.75) -> (14.15, 24.75)
  line L4 (10.5, 22.6) -> (10.5, 24.4)
  arc A1 centre (14.15, 22.6) radius 0.35 clockwise from (14.5, 22.6) to (14.15, 22.25)
  arc A2 centre (14.15, 24.4) radius 0.35 clockwise from (14.15, 24.75) to (14.5, 24.4)
  arc A3 centre (10.85, 24.4) radius 0.35 clockwise from (10.5, 24.4) to (10.85, 24.75)
  arc A4 centre (10.85, 22.6) radius 0.35 clockwise from (10.85, 22.25) to (10.5, 22.6)
extrude "Extrude1" new body sketch "C2 ceramic body profile" blind 4 from offset 10.6 bodies "C2 ceramic body"
sketch "C2 leads profile" plane through (0, 0, 0) normal (0, 0, 1) x axis (1, 0, 0)
  circle C1 centre (15, 23.5) radius 0.275
  circle C2 centre (10, 23.5) radius 0.275
extrude "Extrude2" new body sketch "C2 leads profile" blind 4.2 from offset 6.5 bodies "C2 leads", "C2 leads (1)"
sketch "C4 ceramic body profile" plane through (0, 0, 0) normal (0, 0, 1) x axis (1, 0, 0)
  line L1 (0.4, 29) -> (-1.4, 29)
  line L2 (0.75, 32.65) -> (0.75, 29.35)
  line L3 (-1.4, 33) -> (0.4, 33)
  line L4 (-1.75, 29.35) -> (-1.75, 32.65)
  arc A1 centre (0.4, 29.35) radius 0.35 clockwise from (0.75, 29.35) to (0.4, 29)
  arc A2 centre (0.4, 32.65) radius 0.35 clockwise from (0.4, 33) to (0.75, 32.65)
  arc A3 centre (-1.4, 32.65) radius 0.35 clockwise from (-1.75, 32.65) to (-1.4, 33)
  arc A4 centre (-1.4, 29.35) radius 0.35 clockwise from (-1.4, 29) to (-1.75, 29.35)
extrude "Extrude1" new body sketch "C4 ceramic body profile" blind 4 from offset 10.6 bodies "C4 ceramic body"
sketch "C4 leads profile" plane through (0, 0, 0) normal (0, 0, 1) x axis (1, 0, 0)
  circle C1 centre (-0.5, 28.5) radius 0.275
  circle C2 centre (-0.5, 33.5) radius 0.275
extrude "Extrude2" new body sketch "C4 leads profile" blind 4.2 from offset 6.5 bodies "C4 leads", "C4 leads (1)"
sketch "C10 ceramic body profile" plane through (0, 0, 0) normal (0, 0, 1) x axis (1, 0, 0)
  line L1 (14.15, -4.75) -> (10.85, -4.75)
  line L2 (14.5, -2.6) -> (14.5, -4.4)
  line L3 (10.85, -2.25) -> (14.15, -2.25)
  line L4 (10.5, -4.4) -> (10.5, -2.6)
  arc A1 centre (14.15, -4.4) radius 0.35 clockwise from (14.5, -4.4) to (14.15, -4.75)
  arc A2 centre (14.15, -2.6) radius 0.35 clockwise from (14.15, -2.25) to (14.5, -2.6)
  arc A3 centre (10.85, -2.6) radius 0.35 clockwise from (10.5, -2.6) to (10.85, -2.25)
  arc A4 centre (10.85, -4.4) radius 0.35 clockwise from (10.85, -4.75) to (10.5, -4.4)
extrude "Extrude1" new body sketch "C10 ceramic body profile" blind 4 from offset 10.6 bodies "C10 ceramic body"
sketch "C10 leads profile" plane through (0, 0, 0) normal (0, 0, 1) x axis (1, 0, 0)
  circle C1 centre (15, -3.5) radius 0.275
  circle C2 centre (10, -3.5) radius 0.275
extrude "Extrude2" new body sketch "C10 leads profile" blind 4.2 from offset 6.5 bodies "C10 leads", "C10 leads (1)"
sketch "C11 ceramic body profile" plane through (0, 0, 0) normal (0, 0, 1) x axis (1, 0, 0)
  line L1 (14.15, 3.25) -> (10.85, 3.25)
  line L2 (14.5, 5.4) -> (14.5, 3.6)
  line L3 (10.85, 5.75) -> (14.15, 5.75)
  line L4 (10.5, 3.6) -> (10.5, 5.4)
  arc A1 centre (14.15, 3.6) radius 0.35 clockwise from (14.5, 3.6) to (14.15, 3.25)
  arc A2 centre (14.15, 5.4) radius 0.35 clockwise from (14.15, 5.75) to (14.5, 5.4)
  arc A3 centre (10.85, 5.4) radius 0.35 clockwise from (10.5, 5.4) to (10.85, 5.75)
  arc A4 centre (10.85, 3.6) radius 0.35 clockwise from (10.85, 3.25) to (10.5, 3.6)
extrude "Extrude1" new body sketch "C11 ceramic body profile" blind 4 from offset 10.6 bodies "C11 ceramic body"
sketch "C11 leads profile" plane through (0, 0, 0) normal (0, 0, 1) x axis (1, 0, 0)
  circle C1 centre (15, 4.5) radius 0.275
  circle C2 centre (10, 4.5) radius 0.275
extrude "Extrude2" new body sketch "C11 leads profile" blind 4.2 from offset 6.5 bodies "C11 leads", "C11 leads (1)"
sketch "C12 ceramic body profile" plane through (0, 0, 0) normal (0, 0, 1) x axis (1, 0, 0)
  line L1 (14.15, 11.25) -> (10.85, 11.25)
  line L2 (14.5, 13.4) -> (14.5, 11.6)
  line L3 (10.85, 13.75) -> (14.15, 13.75)
  line L4 (10.5, 11.6) -> (10.5, 13.4)
  arc A1 centre (14.15, 11.6) radius 0.35 clockwise from (14.5, 11.6) to (14.15, 11.25)
  arc A2 centre (14.15, 13.4) radius 0.35 clockwise from (14.15, 13.75) to (14.5, 13.4)
  arc A3 centre (10.85, 13.4) radius 0.35 clockwise from (10.5, 13.4) to (10.85, 13.75)
  arc A4 centre (10.85, 11.6) radius 0.35 clockwise from (10.85, 11.25) to (10.5, 11.6)
extrude "Extrude1" new body sketch "C12 ceramic body profile" blind 4 from offset 10.6 bodies "C12 ceramic body"
sketch "C12 leads profile" plane through (0, 0, 0) normal (0, 0, 1) x axis (1, 0, 0)
  circle C1 centre (15, 12.5) radius 0.275
  circle C2 centre (10, 12.5) radius 0.275
extrude "Extrude2" new body sketch "C12 leads profile" blind 4.2 from offset 6.5 bodies "C12 leads", "C12 leads (1)"
sketch "K1 relay case profile" plane through (0, 0, 0) normal (0, 0, 1) x axis (1, 0, 0)
  line L1 (0.75, 3.5) -> (-9.05, 3.5)
  line L2 (1, 23.55) -> (1, 3.75)
  line L3 (-9.05, 23.8) -> (0.75, 23.8)
  line L4 (-9.3, 3.75) -> (-9.3, 23.55)
  arc A1 centre (0.75, 3.75) radius 0.25 clockwise from (1, 3.75) to (0.75, 3.5)
  arc A2 centre (0.75, 23.55) radius 0.25 clockwise from (0.75, 23.8) to (1, 23.55)
  arc A3 centre (-9.05, 23.55) radius 0.25 clockwise from (-9.3, 23.55) to (-9.05, 23.8)
  arc A4 centre (-9.05, 3.75) radius 0.25 clockwise from (-9.05, 3.5) to (-9.3, 3.75)
extrude "Extrude1" new body sketch "K1 relay case profile" blind 15.8 from offset 9.5 bodies "K1 relay case"
sketch "K1 leads profile" plane through (0, 0, 0) normal (0, 0, 1) x axis (1, 0, 0)
  circle C1 centre (-0.34, 4.83) radius 0.35
  circle C2 centre (-0.34, 14.99) radius 0.35
  circle C3 centre (-0.34, 22.61) radius 0.35
  circle C4 centre (-7.96, 20.07) radius 0.35
  circle C5 centre (-7.96, 4.83) radius 0.35
extrude "Extrude2" new body sketch "K1 leads profile" blind 3.5 from offset 6.5 bodies "K1 leads", "K1 leads (1)", "K1 leads (2)", "K1 leads (3)", "K1 leads (4)"
sketch "U2 converter case profile" plane through (0, 0, 0) normal (0, 0, 1) x axis (1, 0, 0)
  line L1 (17.26, 27.81) -> (3.66, 27.81)
  line L2 (17.46, 35.21) -> (17.46, 28.01)
  line L3 (3.66, 35.41) -> (17.26, 35.41)
  line L4 (3.46, 28.01) -> (3.46, 35.21)
  arc A1 centre (17.26, 28.01) radius 0.2 clockwise from (17.46, 28.01) to (17.26, 27.81)
  arc A2 centre (17.26, 35.21) radius 0.2 clockwise from (17.26, 35.41) to (17.46, 35.21)
  arc A3 centre (3.66, 35.21) radius 0.2 clockwise from (3.46, 35.21) to (3.66, 35.41)
  arc A4 centre (3.66, 28.01) radius 0.2 clockwise from (3.66, 27.81) to (3.46, 28.01)
extrude "Extrude1" new body sketch "U2 converter case profile" blind 10.2 from offset 9.1 bodies "U2 converter case"
sketch "U2 leads profile" plane through (0, 0, 0) normal (0, 0, 1) x axis (1, 0, 0)
  circle C1 centre (13, 29.25) radius 0.32
  circle C2 centre (10.46, 29.25) radius 0.32
  circle C3 centre (7.92, 29.25) radius 0.32
extrude "Extrude2" new body sketch "U2 leads profile" blind 3.5 from offset 6.5 bodies "U2 leads", "U2 leads (1)", "U2 leads (2)"
sketch "Q1 insulating support profile" plane through (0, 0, 0) normal (0, 0, 1) x axis (1, 0, 0)
  line L1 (-10.84, -22.855) -> (-20.84, -22.855)
  line L2 (-10.64, -6.855) -> (-10.64, -22.655)
  line L3 (-20.84, -6.655) -> (-10.84, -6.655)
  line L4 (-21.04, -22.655) -> (-21.04, -6.855)
  arc A1 centre (-10.84, -22.655) radius 0.2 clockwise from (-10.64, -22.655) to (-10.84, -22.855)
  arc A2 centre (-10.84, -6.855) radius 0.2 clockwise from (-10.84, -6.655) to (-10.64, -6.855)
  arc A3 centre (-20.84, -6.855) radius 0.2 clockwise from (-21.04, -6.855) to (-20.84, -6.655)
  arc A4 centre (-20.84, -22.655) radius 0.2 clockwise from (-20.84, -22.855) to (-21.04, -22.655)
extrude "Extrude1" new body sketch "Q1 insulating support profile" blind 1 from offset 9.1 bodies "Q1 insulating support"
sketch "Q1 metal tab profile" plane through (0, 0, 0) normal (0, 0, 1) x axis (1, 0, 0)
  line L1 (-10.705, -23.01) -> (-20.975, -23.01)
  line L2 (-10.505, -6.7) -> (-10.505, -22.81)
  line L3 (-20.975, -6.5) -> (-10.705, -6.5)
  line L4 (-21.175, -22.81) -> (-21.175, -6.7)
  arc A1 centre (-10.705, -22.81) radius 0.2 clockwise from (-10.505, -22.81) to (-10.705, -23.01)
  arc A2 centre (-10.705, -6.7) radius 0.2 clockwise from (-10.705, -6.5) to (-10.505, -6.7)
  arc A3 centre (-20.975, -6.7) radius 0.2 clockwise from (-21.175, -6.7) to (-20.975, -6.5)
  arc A4 centre (-20.975, -22.81) radius 0.2 clockwise from (-20.975, -23.01) to (-21.175, -22.81)
extrude "Extrude2" new body sketch "Q1 metal tab profile" blind 0.9 from offset 10.1 bodies "Q1 metal tab"
sketch "Q1 tab screw hole profile" plane through (0, 0, 0) normal (0, 0, 1) x axis (1, 0, 0)
  circle C1 centre (-15.84, -20.03) radius 2.04
extrude "Extrude3" cut sketch "Q1 tab screw hole profile" blind 1 from offset 10.08
sketch "Q1 molded body profile" plane through (0, 0, 0) normal (0, 0, 1) x axis (1, 0, 0)
  line L1 (-10.705, -16.15) -> (-20.975, -16.15)
  line L2 (-10.505, -6.7) -> (-10.505, -15.95)
  line L3 (-20.975, -6.5) -> (-10.705, -6.5)
  line L4 (-21.175, -15.95) -> (-21.175, -6.7)
  arc A1 centre (-10.705, -15.95) radius 0.2 clockwise from (-10.505, -15.95) to (-10.705, -16.15)
  arc A2 centre (-10.705, -6.7) radius 0.2 clockwise from (-10.705, -6.5) to (-10.505, -6.7)
  arc A3 centre (-20.975, -6.7) radius 0.2 clockwise from (-21.175, -6.7) to (-20.975, -6.5)
  arc A4 centre (-20.975, -15.95) radius 0.2 clockwise from (-20.975, -16.15) to (-21.175, -15.95)
extrude "Extrude4" new body sketch "Q1 molded body profile" blind 3.93 from offset 11 bodies "Q1 molded body"
sketch "Q1 bent lead 1 profile" plane through (0, 0, 0) normal (0, 0, 1) x axis (1, 0, 0)
  line L1 (-12.975, -6.5) -> (-13.625, -6.5)
  line L2 (-12.975, -0.5) -> (-12.975, -6.5)
  line L3 (-13.625, -0.5) -> (-12.975, -0.5)
  line L4 (-13.625, -6.5) -> (-13.625, -0.5)
extrude "Extrude5" new body sketch "Q1 bent lead 1 profile" blind 0.5 from offset 11.6 bodies "Q1 bent lead 1"
sketch "Q1 lead tail 1 profile" plane through (0, 0, 0) normal (0, 0, 1) x axis (1, 0, 0)
  circle C1 centre (-13.3, -0.5) radius 0.325
extrude "Extrude6" new body sketch "Q1 lead tail 1 profile" blind 5.8 from offset 6.3 bodies "Q1 lead tail 1"
sketch "Q1 bent lead 2 profile" plane through (0, 0, 0) normal (0, 0, 1) x axis (1, 0, 0)
  line L1 (-15.515, -6.5) -> (-16.165, -6.5)
  line L2 (-15.515, -0.5) -> (-15.515, -6.5)
  line L3 (-16.165, -0.5) -> (-15.515, -0.5)
  line L4 (-16.165, -6.5) -> (-16.165, -0.5)
extrude "Extrude7" new body sketch "Q1 bent lead 2 profile" blind 0.5 from offset 11.6 bodies "Q1 bent lead 2"
sketch "Q1 lead tail 2 profile" plane through (0, 0, 0) normal (0, 0, 1) x axis (1, 0, 0)
  circle C1 centre (-15.84, -0.5) radius 0.325
extrude "Extrude8" new body sketch "Q1 lead tail 2 profile" blind 5.8 from offset 6.3 bodies "Q1 lead tail 2"
sketch "Q1 bent lead 3 profile" plane through (0, 0, 0) normal (0, 0, 1) x axis (1, 0, 0)
  line L1 (-18.055, -6.5) -> (-18.705, -6.5)
  line L2 (-18.055, -0.5) -> (-18.055, -6.5)
  line L3 (-18.705, -0.5) -> (-18.055, -0.5)
  line L4 (-18.705, -6.5) -> (-18.705, -0.5)
extrude "Extrude9" new body sketch "Q1 bent lead 3 profile" blind 0.5 from offset 11.6 bodies "Q1 bent lead 3"
sketch "Q1 lead tail 3 profile" plane through (0, 0, 0) normal (0, 0, 1) x axis (1, 0, 0)
  circle C1 centre (-18.38, -0.5) radius 0.325
extrude "Extrude10" new body sketch "Q1 lead tail 3 profile" blind 5.8 from offset 6.3 bodies "Q1 lead tail 3"
sketch "BZ1 piezo housing profile" plane through (0, 0, 0) normal (0, 0, 1) x axis (1, 0, 0)
  circle C1 centre (23.2, 1.5) radius 6.1
extrude "Extrude1" new body sketch "BZ1 piezo housing profile" blind 7.8 from offset 9.1 bodies "BZ1 piezo housing"
sketch "BZ1 sound opening profile" plane through (0, 0, 0) normal (0, 0, 1) x axis (1, 0, 0)
  circle C1 centre (23.2, 1.5) radius 1.5
extrude "Extrude2" cut sketch "BZ1 sound opening profile" blind 1.22 from offset 15.7
sketch "BZ1 leads profile" plane through (0, 0, 0) normal (0, 0, 1) x axis (1, 0, 0)
  circle C1 centre (25.7, 1.5) radius 0.3
  circle C2 centre (20.7, 1.5) radius 0.3
extrude "Extrude3" new body sketch "BZ1 leads profile" blind 3.5 from offset 6.5 bodies "BZ1 leads", "BZ1 leads (1)"
sketch "J2 RJ45 housing profile" plane through (0, 0, 0) normal (0, 0, 1) x axis (1, 0, 0)
  line L1 (28.175, 37.01) -> (12.825, 37.01)
  line L2 (28.375, 51.8) -> (28.375, 37.21)
  line L3 (12.825, 52) -> (28.175, 52)
  line L4 (12.625, 37.21) -> (12.625, 51.8)
  arc A1 centre (28.175, 37.21) radius 0.2 clockwise from (28.375, 37.21) to (28.175, 37.01)
  arc A2 centre (28.175, 51.8) radius 0.2 clockwise from (28.175, 52) to (28.375, 51.8)
  arc A3 centre (12.825, 51.8) radius 0.2 clockwise from (12.625, 51.8) to (12.825, 52)
  arc A4 centre (12.825, 37.21) radius 0.2 clockwise from (12.825, 37.01) to (12.625, 37.21)
extrude "Extrude1" new body sketch "J2 RJ45 housing profile" blind 13.21 from offset 9.1 bodies "J2 RJ45 housing"
sketch "J2 plug cavity profile" plane through (0, 0, 0) normal (0, 1, 0) x axis (1, 0, 0)
  line L1 (26.2, -11.705) -> (14.8, -11.705)
  line L2 (26.4, -19.505) -> (26.4, -11.905)
  line L3 (14.8, -19.705) -> (26.2, -19.705)
  line L4 (14.6, -11.905) -> (14.6, -19.505)
  arc A1 centre (26.2, -11.905) radius 0.2 clockwise from (26.2, -11.705) to (26.4, -11.905)
  arc A2 centre (26.2, -19.505) radius 0.2 clockwise from (26.4, -19.505) to (26.2, -19.705)
  arc A3 centre (14.8, -19.505) radius 0.2 clockwise from (14.8, -19.705) to (14.6, -19.505)
  arc A4 centre (14.8, -11.905) radius 0.2 clockwise from (14.6, -11.905) to (14.8, -11.705)
extrude "Extrude2" cut sketch "J2 plug cavity profile" blind 3.03 from offset 49
sketch "J2 latch recess profile" plane through (0, 0, 0) normal (0, 1, 0) x axis (1, 0, 0)
  line L1 (22.9, -10.2) -> (18.1, -10.2)
  line L2 (23, -11.6) -> (23, -10.3)
  line L3 (18.1, -11.7) -> (22.9, -11.7)
  line L4 (18, -10.3) -> (18, -11.6)
  arc A1 centre (22.9, -10.3) radius 0.1 clockwise from (22.9, -10.2) to (23, -10.3)
  arc A2 centre (22.9, -11.6) radius 0.1 clockwise from (23, -11.6) to (22.9, -11.7)
  arc A3 centre (18.1, -11.6) radius 0.1 clockwise from (18.1, -11.7) to (18, -11.6)
  arc A4 centre (18.1, -10.3) radius 0.1 clockwise from (18, -10.3) to (18.1, -10.2)
extrude "Extrude3" cut sketch "J2 latch recess profile" blind 2.03 from offset 50
sketch "J2 contact 1 profile" plane through (0, 0, 0) normal (0, 0, 1) x axis (1, 0, 0)
  line L1 (17.035, 49.05) -> (16.765, 49.05)
  line L2 (17.075, 51.51) -> (17.075, 49.09)
  line L3 (16.765, 51.55) -> (17.035, 51.55)
  line L4 (16.725, 49.09) -> (16.725, 51.51)
  arc A1 centre (17.035, 49.09) radius 0.04 clockwise from (17.075, 49.09) to (17.035, 49.05)
  arc A2 centre (17.035, 51.51) radius 0.04 clockwise from (17.035, 51.55) to (17.075, 51.51)
  arc A3 centre (16.765, 51.51) radius 0.04 clockwise from (16.725, 51.51) to (16.765, 51.55)
  arc A4 centre (16.765, 49.09) radius 0.04 clockwise from (16.765, 49.05) to (16.725, 49.09)
extrude "Extrude4" new body sketch "J2 contact 1 profile" blind 0.12 from offset 11.78 bodies "J2 contact 1"
sketch "J2 contact 2 profile" plane through (0, 0, 0) normal (0, 0, 1) x axis (1, 0, 0)
  line L1 (18.055, 49.05) -> (17.785, 49.05)
  line L2 (18.095, 51.51) -> (18.095, 49.09)
  line L3 (17.785, 51.55) -> (18.055, 51.55)
  line L4 (17.745, 49.09) -> (17.745, 51.51)
  arc A1 centre (18.055, 49.09) radius 0.04 clockwise from (18.095, 49.09) to (18.055, 49.05)
  arc A2 centre (18.055, 51.51) radius 0.04 clockwise from (18.055, 51.55) to (18.095, 51.51)
  arc A3 centre (17.785, 51.51) radius 0.04 clockwise from (17.745, 51.51) to (17.785, 51.55)
  arc A4 centre (17.785, 49.09) radius 0.04 clockwise from (17.785, 49.05) to (17.745, 49.09)
extrude "Extrude5" new body sketch "J2 contact 2 profile" blind 0.12 from offset 11.78 bodies "J2 contact 2"
sketch "J2 contact 3 profile" plane through (0, 0, 0) normal (0, 0, 1) x axis (1, 0, 0)
  line L1 (19.075, 49.05) -> (18.805, 49.05)
  line L2 (19.115, 51.51) -> (19.115, 49.09)
  line L3 (18.805, 51.55) -> (19.075, 51.55)
  line L4 (18.765, 49.09) -> (18.765, 51.51)
  arc A1 centre (19.075, 49.09) radius 0.04 clockwise from (19.115, 49.09) to (19.075, 49.05)
  arc A2 centre (19.075, 51.51) radius 0.04 clockwise from (19.075, 51.55) to (19.115, 51.51)
  arc A3 centre (18.805, 51.51) radius 0.04 clockwise from (18.765, 51.51) to (18.805, 51.55)
  arc A4 centre (18.805, 49.09) radius 0.04 clockwise from (18.805, 49.05) to (18.765, 49.09)
extrude "Extrude6" new body sketch "J2 contact 3 profile" blind 0.12 from offset 11.78 bodies "J2 contact 3"
sketch "J2 contact 4 profile" plane through (0, 0, 0) normal (0, 0, 1) x axis (1, 0, 0)
  line L1 (20.095, 49.05) -> (19.825, 49.05)
  line L2 (20.135, 51.51) -> (20.135, 49.09)
  line L3 (19.825, 51.55) -> (20.095, 51.55)
  line L4 (19.785, 49.09) -> (19.785, 51.51)
  arc A1 centre (20.095, 49.09) radius 0.04 clockwise from (20.135, 49.09) to (20.095, 49.05)
  arc A2 centre (20.095, 51.51) radius 0.04 clockwise from (20.095, 51.55) to (20.135, 51.51)
  arc A3 centre (19.825, 51.51) radius 0.04 clockwise from (19.785, 51.51) to (19.825, 51.55)
  arc A4 centre (19.825, 49.09) radius 0.04 clockwise from (19.825, 49.05) to (19.785, 49.09)
extrude "Extrude7" new body sketch "J2 contact 4 profile" blind 0.12 from offset 11.78 bodies "J2 contact 4"
sketch "J2 contact 5 profile" plane through (0, 0, 0) normal (0, 0, 1) x axis (1, 0, 0)
  line L1 (21.115, 49.05) -> (20.845, 49.05)
  line L2 (21.155, 51.51) -> (21.155, 49.09)
  line L3 (20.845, 51.55) -> (21.115, 51.55)
  line L4 (20.805, 49.09) -> (20.805, 51.51)
  arc A1 centre (21.115, 49.09) radius 0.04 clockwise from (21.155, 49.09) to (21.115, 49.05)
  arc A2 centre (21.115, 51.51) radius 0.04 clockwise from (21.115, 51.55) to (21.155, 51.51)
  arc A3 centre (20.845, 51.51) radius 0.04 clockwise from (20.805, 51.51) to (20.845, 51.55)
  arc A4 centre (20.845, 49.09) radius 0.04 clockwise from (20.845, 49.05) to (20.805, 49.09)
